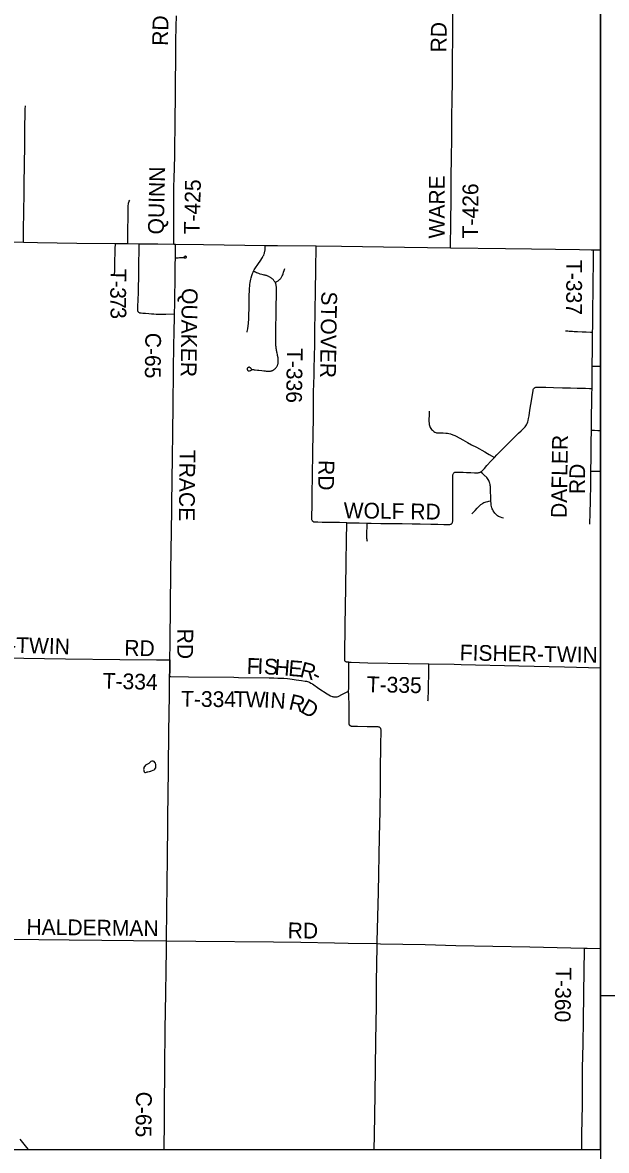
# Model space of a CAD drawing. Extents: x 1341221 to 1914484, y 79347 to 658398.
# Drawn here: x 1414179 to 1435873, y 580393 to 622283 of the extents above; entities that cross this region are included whole.
import ezdxf

# ---------------------------------------------------------------- set-up
doc = ezdxf.new("R2010")
doc.units = 0
for name, color, linetype in [('GM_X_County', 7, 'Continuous'), ('GM_X_Major_Lake_Text', 7, 'Continuous'), ('GM_X_Major_River_Text', 7, 'Continuous'), ('GM_X_Minor_Lake_Text', 7, 'Continuous'), ('GM_X_Section', 7, 'Continuous'), ('GM_X_Township_Text', 7, 'Continuous'), ('GM_X_Unincorporated', 7, 'Continuous'), ('GM_X_US_Shield', 7, 'Continuous')]:
    doc.layers.add(name, color=color, linetype=linetype)

msp = doc.modelspace()

# ---------------------------------------------------------------- linework, layer by layer
at = {"layer": 'GM_X_County'}
msp.add_lwpolyline([(1414396, 580425), (1414339, 580499), (1414093, 580817)], dxfattribs=at)
at = {"layer": 'GM_X_Minor_Lake_Text'}
for p, q in [((1435649, 656148), (1435649, 561648)), ((1435650, 586144), (1485221, 586144))]:
    msp.add_line(p, q, dxfattribs=at)
msp.add_lwpolyline([(1435650, 641695), (1348099, 641695), (1348099, 580425), (1435650, 580425)], close=True, dxfattribs=at)
at = {"layer": 'GM_X_Section'}
for points in [[(1419075, 594833), (1419032, 594853), (1419004, 594850), (1418981, 594847), (1418949, 594832), (1418920, 594813), (1418892, 594787), (1418868, 594768), (1418840, 594753), (1418816, 594742), (1418743, 594696), (1418719, 594670), (1418706, 594647), (1418690, 594616), (1418681, 594581), (1418676, 594542), (1418679, 594514), (1418682, 594491), (1418693, 594459), (1418716, 594431), (1418748, 594434), (1418780, 594442), (1418804, 594449), (1418832, 594456), (1418881, 594466)], [(1418881, 594466), (1418895, 594470), (1418927, 594477), (1418951, 594484), (1418975, 594495), (1419031, 594517), (1419063, 594532), (1419095, 594555), (1419124, 594585), (1419132, 594609), (1419137, 594632), (1419130, 594679), (1419131, 594702), (1419128, 594730), (1419121, 594757), (1419117, 594781), (1419098, 594805), (1419075, 594833)]]:
    msp.add_lwpolyline(points, dxfattribs=at)
at = {"layer": 'GM_X_Township_Text'}
for points in [[(1430084, 613922), (1430084, 613959), (1430092, 614850), (1430100, 615750), (1430106, 616492), (1430114, 617323), (1430124, 617913), (1430132, 618801), (1430139, 619406), (1430150, 620132), (1430158, 620546), (1430158, 620977), (1430162, 621670), (1430168, 622184), (1430179, 623153), (1430184, 623764), (1430191, 624123)], [(1419803, 614052), (1419801, 614083), (1419800, 614109), (1419800, 614130), (1419797, 614180), (1419797, 614222), (1419799, 614548), (1419804, 615309), (1419802, 615551), (1419796, 615870), (1419794, 616004), (1419795, 616135), (1419812, 616551), (1419824, 616843), (1419832, 617396), (1419836, 617683), (1419844, 618419), (1419847, 618602), (1419849, 618829), (1419853, 618974), (1419856, 619234), (1419857, 619500), (1419860, 619704), (1419862, 619897), (1419865, 620221), (1419871, 620750), (1419871, 621209), (1419874, 621595), (1419887, 622141), (1419900, 622537)], [(1414209, 614122), (1414210, 614171), (1414211, 614273), (1414213, 614375), (1414216, 614527), (1414218, 614657), (1414220, 614852), (1414222, 614977), (1414226, 615146), (1414229, 615264), (1414231, 615482), (1414234, 615713), (1414236, 615868), (1414238, 616072), (1414239, 616158), (1414240, 616292), (1414244, 616522), (1414247, 616761), (1414250, 616961), (1414254, 617237), (1414258, 617488), (1414259, 617563), (1414260, 617629), (1414261, 617717), (1414261, 617798), (1414261, 617902), (1414261, 617997), (1414261, 618074), (1414263, 618201), (1414264, 618297), (1414265, 618403), (1414266, 618487), (1414268, 618569), (1414272, 618734), (1414275, 618845), (1414277, 618952), (1414280, 619066), (1414283, 619190)], [(1418090, 614071), (1418090, 614123), (1418094, 614505), (1418096, 614719), (1418099, 614923), (1418102, 615083), (1418102, 615351), (1418105, 615491), (1418110, 615542), (1418116, 615580), (1418127, 615617), (1418141, 615654), (1418159, 615689)], [(1417600, 612892), (1417603, 613104), (1417604, 613195), (1417606, 613356), (1417613, 613526), (1417615, 613630), (1417621, 613830), (1417625, 613922), (1417628, 614031), (1417629, 614076)], [(1419825, 611447), (1419504, 611442), (1419291, 611442), (1419213, 611443), (1419140, 611444), (1419056, 611448), (1418968, 611453), (1418872, 611462), (1418742, 611473), (1418653, 611481), (1418581, 611487), (1418542, 611494), (1418518, 611502), (1418504, 611512), (1418487, 611526), (1418478, 611538), (1418472, 611550), (1418466, 611567), (1418464, 611584), (1418462, 611620), (1418462, 611655), (1418466, 611781), (1418470, 611935), (1418482, 612305), (1418494, 612965), (1418499, 613244), (1418503, 613396), (1418510, 613773), (1418514, 614041), (1418515, 614067)], [(1422520, 610783), (1422527, 610814), (1422544, 610909), (1422570, 611112), (1422573, 611143), (1422574, 611156), (1422581, 611245), (1422589, 611436), (1422593, 611647), (1422594, 611762), (1422598, 612012), (1422601, 612120), (1422614, 612356), (1422627, 612548), (1422636, 612630), (1422645, 612694), (1422655, 612750), (1422669, 612806), (1422694, 612885), (1422721, 612957), (1422748, 613015), (1422764, 613046), (1422790, 613094), (1422839, 613176), (1422917, 613293), (1423030, 613455), (1423068, 613514), (1423096, 613559), (1423112, 613591), (1423124, 613618), (1423138, 613647), (1423152, 613687), (1423164, 613723), (1423172, 613751), (1423178, 613779), (1423183, 613803), (1423187, 613829), (1423190, 613861), (1423194, 613909), (1423197, 613962), (1423200, 614008)], [(1424989, 603737), (1424972, 603746), (1424957, 603759), (1424947, 603773), (1424941, 603784), (1424937, 603794), (1424932, 603811), (1424929, 603830), (1424929, 603874), (1424930, 603961), (1424932, 604060), (1424934, 604220), (1424938, 604551), (1424942, 605015), (1424946, 605214), (1424952, 605601), (1424961, 606168), (1424965, 606431), (1424973, 606907), (1424981, 607175), (1424983, 607420), (1424985, 607610), (1424986, 607721), (1424986, 608105), (1424986, 608406), (1424989, 608558), (1425001, 608877), (1425012, 609176), (1425014, 609298), (1425019, 609539), (1425025, 609783), (1425033, 610420), (1425035, 610517), (1425039, 610747), (1425043, 611055), (1425046, 611307), (1425049, 611533), (1425053, 611737), (1425061, 612157), (1425064, 612375), (1425068, 612589), (1425073, 612832), (1425077, 613121), (1425080, 613438), (1425083, 613659), (1425088, 613969), (1425088, 613986)], [(1426221, 603708), (1426439, 603703), (1426686, 603698), (1426981, 603691), (1427132, 603689), (1427489, 603683), (1427734, 603680), (1427990, 603677), (1428289, 603674), (1428649, 603667), (1428954, 603661), (1429349, 603654), (1429602, 603650), (1429829, 603646), (1430023, 603641), (1430059, 603642), (1430084, 603647), (1430102, 603654), (1430118, 603664), (1430131, 603678), (1430142, 603692), (1430151, 603712), (1430157, 603735), (1430163, 603769), (1430165, 603792), (1430167, 603848), (1430167, 604008), (1430165, 604332), (1430163, 604579), (1430163, 604817), (1430163, 604983), (1430163, 605103), (1430164, 605259), (1430165, 605383), (1430166, 605446), (1430167, 605464), (1430170, 605489), (1430176, 605513), (1430187, 605536), (1430200, 605553), (1430219, 605569), (1430237, 605580), (1430257, 605586), (1430282, 605589), (1430313, 605589), (1430371, 605587), (1430449, 605584), (1430552, 605579), (1430669, 605574), (1430828, 605568), (1430965, 605563), (1431034, 605562), (1431073, 605563), (1431104, 605565), (1431135, 605570), (1431159, 605576), (1431179, 605584), (1431199, 605596), (1431227, 605614), (1431251, 605632), (1431272, 605650), (1431287, 605666), (1431308, 605687), (1431337, 605722), (1431427, 605826), (1431587, 606003), (1431712, 606132), (1431805, 606229), (1431926, 606352), (1432144, 606575), (1432231, 606663), (1432402, 606836), (1432502, 606934), (1432568, 606996), (1432604, 607031), (1432699, 607118), (1432755, 607170), (1432814, 607228), (1432852, 607270), (1432883, 607311), (1432907, 607348), (1432929, 607394), (1432949, 607448), (1432963, 607497), (1432981, 607578), (1432997, 607673), (1433029, 607887), (1433062, 608103), (1433084, 608237), (1433144, 608615), (1433154, 608652), (1433164, 608675), (1433178, 608696), (1433191, 608710), (1433207, 608721), (1433230, 608731), (1433253, 608738), (1433285, 608742), (1433317, 608743), (1433376, 608743), (1433459, 608741), (1433618, 608736), (1433902, 608727), (1434241, 608718), (1434535, 608711), (1434791, 608705), (1434911, 608702), (1435094, 608699), (1435239, 608695), (1435336, 608693), (1435338, 608833), (1435340, 608985), (1435341, 609124), (1435342, 609388), (1435343, 609524), (1435347, 609720), (1435352, 609952), (1435353, 610176), (1435355, 610433), (1435358, 610612), (1435360, 610782), (1435362, 610968), (1435365, 611109), (1435366, 611403), (1435368, 611524), (1435370, 611633), (1435372, 611830), (1435374, 612134), (1435379, 612414), (1435384, 612803), (1435390, 613197), (1435394, 613461), (1435395, 613612), (1435395, 613842)], [(1419856, 613544), (1419898, 613547), (1419956, 613550), (1420004, 613553), (1420041, 613555), (1420075, 613557), (1420109, 613558), (1420136, 613557), (1420157, 613556), (1420168, 613552), (1420188, 613546), (1420199, 613543), (1420214, 613542), (1420233, 613542), (1420245, 613543), (1420252, 613545), (1420257, 613550), (1420263, 613559), (1420266, 613570), (1420265, 613582), (1420259, 613592), (1420252, 613599), (1420243, 613602), (1420232, 613603), (1420221, 613600), (1420211, 613596), (1420202, 613591), (1420193, 613585), (1420180, 613575), (1420170, 613566), (1420161, 613558)], [(1422697, 609392), (1422688, 609408), (1422682, 609416), (1422677, 609424), (1422670, 609433), (1422663, 609441), (1422653, 609450), (1422644, 609458), (1422635, 609465), (1422624, 609472), (1422615, 609476), (1422606, 609478), (1422597, 609479), (1422587, 609479), (1422578, 609477), (1422568, 609475), (1422557, 609469), (1422549, 609463), (1422542, 609457), (1422535, 609446), (1422530, 609437), (1422527, 609429), (1422525, 609418), (1422524, 609410), (1422526, 609399), (1422527, 609391), (1422532, 609379), (1422539, 609369), (1422546, 609362), (1422553, 609356), (1422562, 609350), (1422570, 609347), (1422580, 609344), (1422589, 609342), (1422599, 609341), (1422608, 609342), (1422617, 609343), (1422627, 609345), (1422639, 609350), (1422650, 609355), (1422672, 609368), (1422694, 609383), (1422703, 609388), (1422711, 609391), (1422717, 609393), (1422723, 609395), (1422728, 609395), (1422735, 609395), (1422754, 609394), (1422779, 609390), (1422824, 609385), (1422906, 609375), (1422962, 609369), (1423070, 609357), (1423139, 609350), (1423196, 609344), (1423235, 609340), (1423254, 609339), (1423274, 609338), (1423298, 609336), (1423329, 609336), (1423362, 609337), (1423394, 609339), (1423412, 609343), (1423426, 609346), (1423443, 609351), (1423456, 609356), (1423476, 609365), (1423491, 609373), (1423506, 609381), (1423518, 609389), (1423530, 609398), (1423545, 609409), (1423557, 609419), (1423574, 609436), (1423589, 609454), (1423602, 609470), (1423615, 609489), (1423626, 609510), (1423634, 609524), (1423645, 609546), (1423654, 609564), (1423662, 609584), (1423667, 609600), (1423672, 609619), (1423676, 609638), (1423679, 609660), (1423681, 609682), (1423682, 609706), (1423682, 609727), (1423680, 609756), (1423679, 609779), (1423676, 609801), (1423672, 609830), (1423667, 609862), (1423662, 609884), (1423656, 609912), (1423647, 609958), (1423639, 610000), (1423632, 610035), (1423626, 610067), (1423619, 610101), (1423613, 610134), (1423606, 610176), (1423599, 610222), (1423596, 610248), (1423594, 610269), (1423592, 610290), (1423591, 610310), (1423589, 610331), (1423588, 610352), (1423587, 610377), (1423586, 610398), (1423586, 610419), (1423586, 610447), (1423585, 610473), (1423585, 610513), (1423585, 610553), (1423585, 610601), (1423588, 610713), (1423589, 610794), (1423591, 610900), (1423594, 611088), (1423597, 611289), (1423601, 611523), (1423604, 611693), (1423605, 611796), (1423607, 611901), (1423608, 612009), (1423610, 612150), (1423612, 612252), (1423613, 612310), (1423613, 612347), (1423612, 612371), (1423612, 612399), (1423610, 612438), (1423608, 612467), (1423606, 612487), (1423603, 612514), (1423598, 612538), (1423592, 612562), (1423584, 612587), (1423578, 612605), (1423573, 612619), (1423565, 612633), (1423555, 612651), (1423545, 612667), (1423532, 612684), (1423517, 612703), (1423497, 612727), (1423475, 612749), (1423454, 612769), (1423431, 612788), (1423409, 612804), (1423389, 612817), (1423366, 612831), (1423346, 612841), (1423323, 612852), (1423297, 612862), (1423266, 612874), (1423238, 612883), (1423219, 612889), (1423195, 612896), (1423161, 612905), (1423116, 612916), (1423070, 612928), (1423013, 612943), (1422960, 612960), (1422915, 612976), (1422876, 612991), (1422837, 613008), (1422796, 613029), (1422764, 613046)], [(1423565, 612633), (1423601, 612651), (1423631, 612665), (1423657, 612679), (1423681, 612694), (1423706, 612714), (1423731, 612736), (1423751, 612756), (1423766, 612774), (1423784, 612796), (1423799, 612821), (1423815, 612852), (1423829, 612882), (1423844, 612917), (1423857, 612955), (1423877, 613013), (1423897, 613073), (1423926, 613150)], [(1434354, 610839), (1434436, 610829), (1434493, 610822), (1434550, 610818), (1434611, 610815), (1434678, 610811), (1434803, 610806), (1434969, 610799), (1435114, 610793), (1435280, 610786), (1435360, 610782)], [(1435343, 609524), (1435442, 609523), (1435650, 609522)], [(1435252, 603651), (1435258, 603802), (1435263, 603931), (1435267, 604038), (1435272, 604187), (1435278, 604401), (1435281, 604514), (1435284, 604617), (1435286, 604762), (1435288, 604890), (1435290, 605015), (1435291, 605156), (1435296, 605406), (1435297, 605514), (1435297, 605626), (1435298, 605745), (1435300, 606011), (1435302, 606188), (1435304, 606370), (1435306, 606516), (1435311, 606815), (1435314, 607023), (1435316, 607134), (1435317, 607238), (1435318, 607382), (1435320, 607590), (1435322, 607787), (1435325, 608072), (1435327, 608295), (1435331, 608491), (1435336, 608693)], [(1429284, 607853), (1429281, 607673), (1429279, 607564), (1429277, 607462), (1429280, 607398), (1429287, 607354), (1429296, 607316), (1429309, 607280), (1429325, 607246), (1429348, 607207), (1429375, 607172), (1429405, 607139), (1429433, 607113), (1429465, 607091), (1429498, 607073), (1429534, 607059), (1429564, 607050), (1429602, 607044), (1429653, 607041), (1429812, 607042), (1429902, 607038), (1429965, 607032), (1430022, 607022), (1430077, 607007), (1430167, 606975), (1430238, 606946), (1430288, 606919), (1430541, 606781), (1430713, 606684), (1430865, 606602), (1431039, 606507), (1431358, 606334), (1431452, 606281), (1431519, 606243), (1431712, 606132)], [(1435650, 607121), (1435554, 607125), (1435429, 607130), (1435316, 607134)], [(1431569, 604831), (1431568, 604851), (1431564, 604972), (1431559, 605048), (1431555, 605087), (1431550, 605127), (1431541, 605170), (1431529, 605205), (1431517, 605237), (1431501, 605269), (1431479, 605308), (1431451, 605351), (1431423, 605385), (1431391, 605417), (1431368, 605439), (1431337, 605464), (1431264, 605529), (1431223, 605568), (1431199, 605596)], [(1435297, 605626), (1435400, 605623), (1435481, 605620), (1435525, 605620), (1435621, 605619), (1435650, 605620)], [(1430876, 604041), (1430908, 604073), (1430955, 604120), (1430997, 604163), (1431073, 604249), (1431136, 604312), (1431207, 604377), (1431250, 604414), (1431282, 604435), (1431316, 604453), (1431369, 604475), (1431405, 604487), (1431460, 604500), (1431509, 604509), (1431562, 604519), (1431578, 604522)], [(1431577, 604542), (1431576, 604571), (1431575, 604635), (1431573, 604710), (1431569, 604831)], [(1432047, 603874), (1432000, 603890), (1431941, 603910), (1431903, 603926), (1431868, 603943), (1431830, 603966), (1431789, 603997), (1431752, 604031), (1431722, 604065), (1431695, 604100), (1431669, 604144), (1431648, 604184), (1431630, 604223), (1431617, 604257), (1431604, 604304), (1431594, 604354), (1431587, 604404), (1431578, 604522), (1431577, 604542)], [(1426221, 603708), (1425953, 603714), (1425742, 603717), (1425445, 603719), (1425308, 603720), (1425153, 603721), (1425083, 603722), (1425038, 603725), (1425007, 603731), (1424989, 603737)], [(1426297, 598522), (1426258, 598525), (1426239, 598528), (1426220, 598532), (1426200, 598539), (1426191, 598543), (1426183, 598547), (1426176, 598552), (1426170, 598558), (1426164, 598564), (1426159, 598572), (1426156, 598579), (1426153, 598589), (1426151, 598613), (1426148, 598689), (1426150, 598784), (1426166, 599894), (1426191, 601295), (1426203, 602248), (1426211, 603047), (1426221, 603708)], [(1426997, 603007), (1426987, 603050), (1426978, 603087), (1426971, 603126), (1426969, 603152), (1426968, 603180), (1426967, 603216), (1426969, 603288), (1426973, 603375), (1426977, 603534), (1426979, 603617), (1426981, 603691)], [(1409703, 598728), (1409758, 598728), (1410012, 598732), (1411492, 598715), (1413449, 598685), (1415776, 598652), (1417797, 598632), (1419153, 598617), (1419608, 598612), (1419651, 598611)], [(1419651, 598611), (1419646, 598219), (1419643, 597996)], [(1427247, 580425), (1427256, 580960), (1427282, 582468), (1427303, 584460), (1427324, 585764), (1427335, 586762), (1427343, 587196), (1427353, 588073), (1427355, 588114), (1427357, 588153), (1427370, 588613), (1427406, 589982), (1427447, 592035), (1427460, 592994), (1427475, 593965), (1427479, 594500), (1427489, 595451), (1427499, 595983), (1427499, 596001), (1427497, 596019), (1427495, 596038), (1427491, 596053), (1427486, 596065), (1427477, 596078), (1427467, 596090), (1427456, 596100), (1427442, 596109), (1427430, 596114), (1427412, 596119), (1427393, 596123), (1427366, 596126), (1427333, 596127), (1426981, 596129), (1426627, 596134), (1426434, 596136), (1426424, 596136), (1426415, 596138), (1426406, 596140), (1426398, 596142), (1426389, 596145), (1426382, 596148), (1426375, 596151), (1426367, 596155), (1426360, 596160), (1426352, 596165), (1426346, 596171), (1426340, 596177), (1426335, 596183), (1426330, 596191), (1426324, 596202), (1426320, 596212), (1426314, 596236), (1426310, 596260), (1426309, 596289), (1426308, 596869), (1426299, 597343), (1426297, 597368), (1426295, 597378), (1426293, 597386), (1426289, 597396), (1426289, 597414), (1426289, 597446), (1426299, 597560), (1426304, 597702), (1426302, 597955), (1426304, 598339), (1426297, 598522)], [(1426297, 598522), (1426385, 598522), (1427002, 598507), (1428509, 598483), (1429275, 598466), (1430214, 598453), (1430469, 598441), (1432615, 598388), (1434309, 598348), (1435650, 598316)], [(1429242, 597086), (1429247, 597126), (1429249, 597157), (1429262, 597477), (1429270, 598271), (1429275, 598466)], [(1419643, 597996), (1419694, 597995), (1420348, 597986), (1422031, 597965), (1422204, 597964), (1423336, 597945), (1423515, 597942), (1423664, 597939), (1423777, 597936), (1423889, 597929), (1424017, 597916), (1424195, 597897), (1424347, 597877), (1424539, 597850), (1424684, 597826), (1424732, 597817), (1424771, 597807), (1424804, 597795), (1424835, 597782), (1424889, 597753), (1424947, 597719), (1425193, 597553), (1425497, 597351), (1425562, 597310), (1425621, 597279), (1425684, 597254), (1425706, 597247), (1425729, 597241), (1425762, 597237), (1425791, 597235), (1425819, 597236), (1425846, 597239), (1425871, 597245), (1425901, 597255), (1426065, 597334), (1426289, 597446)], [(1434960, 580425), (1434961, 580777), (1434963, 580995), (1434977, 582070), (1434980, 582684), (1434984, 583137), (1434987, 583443), (1435004, 584350), (1435015, 585219), (1435034, 586191), (1435043, 587099), (1435052, 587810), (1435053, 587907)]]:
    msp.add_lwpolyline(points, dxfattribs=at)
at = {"layer": 'GM_X_Unincorporated'}
for points in [[(1409912, 614172), (1410597, 614163), (1413316, 614135), (1414209, 614122), (1414730, 614114), (1416201, 614093), (1417629, 614076), (1417647, 614076), (1418090, 614071), (1418515, 614067), (1419201, 614060), (1419803, 614052), (1419866, 614051), (1420908, 614038), (1423200, 614008), (1423652, 614002), (1425088, 613986), (1426031, 613975), (1428365, 613945), (1430084, 613922), (1432126, 613895), (1433092, 613879), (1434871, 613851), (1435308, 613844)], [(1435308, 613844), (1435395, 613842), (1435650, 613838)]]:
    msp.add_lwpolyline(points, dxfattribs=at)
at = {"layer": 'GM_X_US_Shield'}
for points in [[(1419651, 598611), (1419652, 598681), (1419658, 599174), (1419663, 599684), (1419670, 600238), (1419677, 600854), (1419680, 601121), (1419683, 601364), (1419686, 601555), (1419689, 601820), (1419693, 602133), (1419697, 602438), (1419705, 602859), (1419710, 603199), (1419715, 603589), (1419720, 604005), (1419726, 604563), (1419732, 605128), (1419738, 605431), (1419742, 605629), (1419744, 605797), (1419752, 606387), (1419757, 606790), (1419759, 606985), (1419766, 607449), (1419769, 607670), (1419770, 607881), (1419780, 608629), (1419782, 608776), (1419786, 609115), (1419792, 609672), (1419798, 610017), (1419801, 610209), (1419805, 610394), (1419811, 610674), (1419814, 610802), (1419815, 610905), (1419816, 610999), (1419819, 611153), (1419822, 611322), (1419825, 611447), (1419828, 611569), (1419832, 611731), (1419836, 611948), (1419842, 612299), (1419845, 612512), (1419847, 612649), (1419848, 612768), (1419851, 613095), (1419853, 613285), (1419856, 613544), (1419860, 613728), (1419863, 613903), (1419865, 614021), (1419866, 614051)], [(1419643, 597996), (1419646, 598219), (1419651, 598611)], [(1419435, 580425), (1419439, 580716), (1419447, 581189), (1419451, 581432), (1419451, 581656), (1419455, 582206), (1419457, 582488), (1419463, 582936), (1419471, 583806), (1419480, 584544), (1419483, 584897), (1419504, 586223), (1419513, 587083), (1419522, 587844), (1419526, 588176), (1419539, 589361), (1419549, 590214), (1419563, 591344), (1419575, 592429), (1419582, 592920), (1419588, 593471), (1419593, 593855), (1419598, 594298), (1419603, 594690), (1419607, 595115), (1419611, 595416), (1419616, 595755), (1419620, 596094), (1419625, 596471), (1419629, 596780), (1419633, 597141), (1419637, 597546), (1419643, 597996)], [(1409573, 588291), (1410116, 588284), (1411076, 588272), (1412233, 588255), (1413372, 588243), (1414785, 588228), (1415917, 588216), (1417120, 588201), (1418303, 588191), (1419526, 588176), (1420613, 588163), (1423504, 588136), (1424514, 588123), (1425772, 588109), (1426271, 588096), (1427353, 588073), (1427473, 588071), (1429135, 588036), (1430273, 588010), (1433029, 587954), (1435053, 587907), (1435153, 587905), (1435650, 587892)]]:
    msp.add_lwpolyline(points, dxfattribs=at)

# ---------------------------------------------------------------- texts
at = {"layer": 'GM_X_Major_Lake_Text'}
for s, rotation, p in [('QUAKER', 269.1796, (1420101, 612424)), ('C-65', 269.3136, (1418742, 610764)), ('TRACE', 269.3703, (1420015, 606416)), ('RD', 269.5063, (1419936, 599775)), ('HALDERMAN', 359.3538, (1414321, 588406)), ('RD', 359.0128, (1424026, 588277)), ('C-65', 269.3142, (1418398, 582579))]:
    msp.add_text(s, height=585, rotation=rotation, dxfattribs=at).set_placement(p)
at = {"layer": 'GM_X_Major_River_Text'}
for s, rotation, p in [('RD', 89.0118, (1419580, 621414)), ('RD', 89.5063, (1429927, 621170)), ('QUINN', 88.7173, (1419423, 614406)), ('T-425', 88.5962, (1420756, 614408)), ('WARE', 89.7658, (1429858, 614262)), ('T-426', 89.7188, (1431103, 614265)), ('T-337', 269.7188, (1434384, 613468)), ('T', 268.7335, (1417456, 613143)), ('-', 268.8102, (1417446, 612704)), ('3', 269.0776, (1417441, 612461)), ('7', 270.1392, (1417435, 612089)), ('STOVER', 269.116, (1425282, 612301)), ('3', 273.1593, (1417437, 611695)), ('T-336', 269.1574, (1424002, 610201)), ('DAFLER', 89.116, (1434396, 603878)), ('RD', 269.0118, (1425179, 606038)), ('RD', 89.5063, (1435075, 604766)), ('WOLF RD', 359.079, (1426105, 603878)), ('FISHER-TWIN', 358.4926, (1410806, 598953)), ('RD', 358.5175, (1417953, 598773)), ('FISHER-TWIN', 359.0305, (1430418, 598593)), ('F', 359.1447, (1422506, 598095)), ('I', 358.2356, (1422898, 598089)), ('S', 356.9244, (1423135, 598082)), ('H', 355.7596, (1423526, 598061)), ('E', 355.044, (1424037, 598023)), ('R', 345.2443, (1424447, 597990)), ('T-334', 358.5957, (1417150, 597545)), ('-', 331.8306, (1424878, 597881)), ('T-335', 358.8762, (1426962, 597416)), ('T-334', 359.4375, (1420065, 596875)), ('T', 359.1214, (1422025, 596868)), ('W', 358.492, (1422461, 596861)), ('I', 357.2122, (1423135, 596844)), ('N', 355.8948, (1423371, 596832)), ('R', 346.8091, (1424040, 596785)), ('D', 330.1946, (1424466, 596692)), ('T-360', 268.8768, (1433989, 587203))]:
    msp.add_text(s, height=585, rotation=rotation, dxfattribs=at).set_placement(p)

doc.saveas('drawing.dxf')
